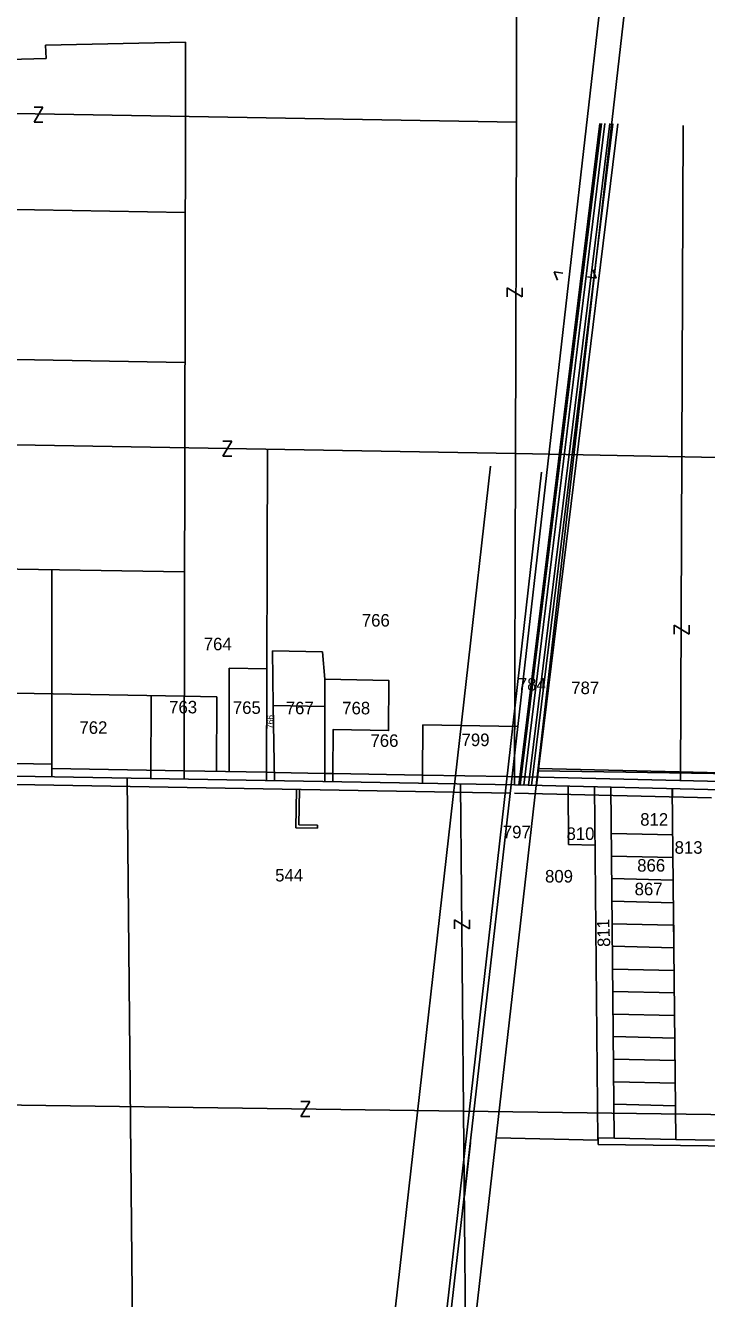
# Model space of a CAD drawing. Extents: x 582596 to 627039, y 145946 to 197316.
# Drawn here: x 610608 to 613327, y 162740 to 167820 of the extents above; entities that cross this region are included whole.
import ezdxf

# ---------------------------------------------------------------- set-up
doc = ezdxf.new("R2010")
doc.units = 0
for name, color, linetype in [('Defpoints 2', 7, 'Continuous'), ('E_RW_EasementUtility', 7, 'Continuous'), ('E_RW_Existing', 7, 'Continuous'), ('E_RW_SixteenthLine', 7, 'Continuous'), ('P_RW_MinorLotLine', 7, 'Continuous'), ('P_RW_PropertyConnector', 7, 'Continuous'), ('P_RW_PropertyLine', 7, 'Continuous'), ('P_RW_QuarterLine', 7, 'Continuous'), ('P_RW_SectionLine', 7, 'Continuous')]:
    doc.layers.add(name, color=color, linetype=linetype)

msp = doc.modelspace()

# ---------------------------------------------------------------- linework, layer by layer
at = {"layer": 'E_RW_EasementUtility'}
for p, q in [((612577.3, 164788.9), (612901.6, 167429.2)), ((612583, 164788.7), (612907.4, 167429.1)), ((612921.7, 167428.8), (612597.4, 164788.4)), ((612940.5, 167428.5), (612616.1, 164788)), ((612952.5, 167428.3), (612628.1, 164787.7)), ((612648.2, 164787.2), (612972.6, 167428)), ((612465.1, 166061), (611596.5, 158385.8)), ((611802.8, 158385.8), (612668.8, 166037.9)), ((612654.1, 164845.1), (613797.7, 164828.8)), ((613797.7, 164828.8), (612655.2, 164855.1)), ((611690.4, 164771.7), (611687.7, 164618.7)), ((611699.9, 164630.5), (611702.4, 164771.4)), ((611687.7, 164618.7), (611773.7, 164617.2)), ((611773.9, 164629.2), (611699.9, 164630.5)), ((611773.9, 164629.2), (611773.7, 164617.2))]:
    msp.add_line(p, q, dxfattribs=at)
at = {"layer": 'E_RW_Existing'}
for p, q in [((610713.5, 164855), (611241.4, 164845.6)), ((611571.3, 164839.8), (611602.3, 164839.2)), ((611802.9, 164835.7), (611835.9, 164835.1)), ((611835.9, 164835.1), (612193.9, 164828.7)), ((612606.8, 164821.2), (613901.2, 164791.4)), ((609921, 164803), (612544.3, 164756.5)), ((612560.3, 164756.2), (613346.3, 164738.1))]:
    msp.add_line(p, q, dxfattribs=at)
at = {"layer": 'E_RW_SixteenthLine'}
for p, q in [((611247.3, 167457.3), (611241.3, 164812.6)), ((609924, 166157.8), (612564.6, 166112.1)), ((612564.6, 166112.1), (615206.7, 166058.7)), ((611039.6, 162177.2), (611014.3, 164816.6)), ((609696.6, 163524.2), (612357.2, 163488.1)), ((612357.2, 163488.1), (615010.7, 163449.6))]:
    msp.add_line(p, q, dxfattribs=at)
at = {"layer": 'P_RW_MinorLotLine'}
for p, q in [((613222.7, 164807), (613233.6, 167421.8)), ((611803.5, 165102.5), (611597.7, 165106.2)), ((612947.2, 164595.4), (613192.2, 164589.7)), ((612949.6, 164325.4), (613195, 164319.2)), ((612947.3, 164235.4), (613192.7, 164229.2)), ((612951.5, 164145.4), (613197.1, 164139.7)), ((613197.9, 164049.2), (612953.2, 164054.8)), ((613203.9, 163374.8), (613359.5, 163371.2))]:
    msp.add_line(p, q, dxfattribs=at)
at = {"layer": 'P_RW_PropertyConnector'}
for p, q in [((610642.5, 167494.7), (610678.1, 167494.7)), ((610678.1, 167494.7), (610642.5, 167434.7)), ((610660.3, 167464.7), (610660.3, 167464.7)), ((610642.5, 167434.7), (610678.1, 167434.7)), ((612732.2, 166803.6), (612718.7, 166836.6)), ((612718.7, 166836.6), (612753.5, 166831.4)), ((612753.2, 166831.4), (612753.2, 166831.4)), ((612886.7, 166811.6), (612851.9, 166816.7)), ((612852.2, 166816.7), (612852.2, 166816.7)), ((612873.2, 166844.6), (612886.7, 166811.6)), ((612531.5, 166773.6), (612531.5, 166737.9)), ((612591.5, 166737.9), (612531.5, 166773.6)), ((612561.5, 166755.8), (612561.5, 166755.8)), ((612591.5, 166773.6), (612591.5, 166737.9)), ((611396.9, 166160.9), (611432.5, 166160.9)), ((611432.5, 166160.9), (611396.9, 166100.9)), ((611396.9, 166100.9), (611432.5, 166100.9)), ((611414.7, 166130.9), (611414.7, 166130.9)), ((613198.2, 165391.5), (613198.2, 165427.2)), ((613198.2, 165427.2), (613258.2, 165391.5)), ((613258.2, 165391.5), (613258.2, 165427.2)), ((613228.2, 165409.4), (613228.2, 165409.4)), ((612320.7, 164215.4), (612320.7, 164251)), ((612320.7, 164251), (612380.6, 164215.4)), ((612350.7, 164233.2), (612350.7, 164233.2)), ((612380.6, 164215.4), (612380.7, 164251)), ((611707.5, 163526.5), (611743.1, 163526.5)), ((611743.1, 163526.5), (611707.5, 163466.5)), ((611725.3, 163496.5), (611725.3, 163496.5)), ((611707.5, 163466.5), (611743.1, 163466.5))]:
    msp.add_line(p, q, dxfattribs=at)
at = {"layer": 'P_RW_PropertyLine'}
for p, q in [((613149.4, 170068.4), (612547.1, 164789.5)), ((613248.8, 170057), (612647.5, 164787.2)), ((610688.3, 167741.6), (611246.6, 167754.2)), ((611247.2, 167754.2), (610688.3, 167741.6)), ((610690.6, 167688.1), (610688.3, 167741.6)), ((610688.3, 167741.6), (610690.6, 167688.1)), ((611246.8, 167457.2), (611247.2, 167754.2)), ((610473.8, 167683.2), (610690.6, 167688.1)), ((610690.6, 167688.1), (610473.8, 167683.2)), ((611246.8, 167457.2), (611246.8, 167457.2)), ((611246.8, 167457.2), (611246.8, 167457.2)), ((612825.1, 167428.9), (612825.1, 167428.8)), ((612825.1, 167428.8), (612825.1, 167428.9)), ((609957.7, 167096.5), (611246, 167074.1)), ((609924.5, 166498.4), (611245.1, 166475.7)), ((611574.3, 166129.2), (611571.2, 164806.8)), ((611243.2, 165639.3), (609923.1, 165662.2)), ((610713.9, 165648.5), (610714.1, 165152.5)), ((611593.9, 165324.2), (611793.9, 165320.7)), ((611597.7, 165106.2), (611593.9, 165324.2)), ((611793.9, 165320.7), (611803.7, 165211.1)), ((611422.2, 165255.1), (611421.3, 164842.4)), ((611422.2, 165255.1), (611572.3, 165252.4)), ((611242.1, 165143.2), (609922.2, 165166.4)), ((610713.5, 164872), (610714.1, 165152.5)), ((611110.1, 165145.5), (611109.4, 164814.9)), ((611372, 165140.9), (611242.1, 165143.2)), ((611371.3, 164843.3), (611372, 165140.9)), ((611597.7, 165106.2), (611602.8, 164806.2)), ((612194.4, 165028.7), (612193.9, 164828.7)), ((612573.6, 165022), (612194.4, 165028.7)), ((609954.6, 164885.4), (610713.5, 164872)), ((610713.4, 164821.9), (610713.5, 164872)), ((611241.4, 164845.6), (611571.3, 164839.8)), ((611802.2, 164835.7), (611602.3, 164839.2)), ((612193.9, 164828.7), (612193.8, 164795.7)), ((612193.9, 164828.7), (612531.2, 164822.8)), ((612531.2, 164822.8), (612561.2, 164822.2)), ((612561.2, 164822.3), (612606.8, 164821.2)), ((611802.9, 164802.7), (611802.8, 164802.7)), ((611945.4, 159522.2), (612547.1, 164789.5)), ((612044.8, 159510.8), (612647.5, 164787.2)), ((612774.4, 164784.3), (612776.7, 164551.3)), ((612879.4, 164781.9), (612892.9, 163372)), ((612945.4, 164780.4), (612958.8, 163379.9)), ((613190.5, 164774.7), (613203.9, 163374.8)), ((613191, 164774.7), (613191.1, 164741.2)), ((613191.1, 164741.2), (613191, 164774.2)), ((612776.7, 164551.3), (612881.6, 164548.9)), ((612948, 164505.4), (613193.1, 164499.7)), ((612948.9, 164415.4), (613194.3, 164409.2)), ((613196.9, 164139.2), (613196.2, 164229.2)), ((612953.2, 163964.9), (613198.7, 163959.2)), ((613199.6, 163869.2), (612955.4, 163874.9)), ((613200.4, 163779.2), (612956.4, 163784.9)), ((613201.3, 163689.2), (612957.1, 163694.9)), ((613202.1, 163599.3), (612958.1, 163604.9)), ((613203, 163509.2), (612958.9, 163514.9)), ((612360.6, 163148.6), (612385, 163360.6)), ((612487.8, 163381.3), (612892.9, 163372)), ((612960.2, 163379.9), (612894.2, 163381.4)), ((612894.2, 163381.4), (612894.5, 163354.6)), ((612894.5, 163354.6), (612894.2, 163381.4)), ((613685.6, 163345.3), (612894.5, 163354.6)), ((613204.4, 163374.2), (612960.2, 163379.9)), ((612360.6, 163148.6), (612360.6, 163148.6))]:
    msp.add_line(p, q, dxfattribs=at)
msp.add_lwpolyline([(611835.7, 164802.1), (611835.8, 164802.1), (611835.9, 164835.1), (611836.3, 165010.5), (612058.2, 165006.5), (612058.7, 165206.5), (611803.7, 165211.1), (611803.3, 165011.1), (611802.9, 164835.7), (611802.8, 164802.7)], dxfattribs=at)
at = {"layer": 'P_RW_QuarterLine'}
for p, q in [((612568.2, 167435), (612570.2, 170074.9)), ((609926.5, 167479.6), (612568.2, 167435)), ((612568.2, 167435), (612561.1, 164789.2)), ((612344.6, 164793.1), (612369.9, 162157.1))]:
    msp.add_line(p, q, dxfattribs=at)
at = {"layer": 'P_RW_SectionLine'}
for p, q in [((609921.6, 164836), (612561.1, 164789.2)), ((612561.1, 164789.2), (615201.2, 164728.4))]:
    msp.add_line(p, q, dxfattribs=at)

# ---------------------------------------------------------------- texts
at = {"layer": 'Defpoints 2'}
for s, p in [('766', (611951.1, 165421.4)), ('764', (611320.1, 165326.8)), ('784', (612573.9, 165165.9)), ('787', (612787.2, 165151.9)), ('763', (611182, 165075)), ('765', (611436.3, 165073)), ('767', (611647.4, 165071.5)), ('768', (611872.9, 165071.1)), ('762', (610823.8, 164993.4)), ('766', (611985.7, 164941.2)), ('799', (612349.3, 164944.4)), ('812', (613062.4, 164626.8)), ('797', (612514, 164576.5)), ('810', (612768.2, 164569.8)), ('813', (613199.7, 164514.9)), ('866', (613050.4, 164443.5)), ('544', (611605.2, 164404.2)), ('809', (612682.5, 164400)), ('867', (613040.1, 164349.1))]:
    msp.add_text(s, height=50, dxfattribs=at).set_placement(p)
for s, height, rotation, p in [('766', 25, 90, (611597.9, 165012.8)), ('811', 50, 92.0871, (612942.8, 164143.8))]:
    msp.add_text(s, height=height, rotation=rotation, dxfattribs=at).set_placement(p)

doc.saveas('drawing.dxf')
